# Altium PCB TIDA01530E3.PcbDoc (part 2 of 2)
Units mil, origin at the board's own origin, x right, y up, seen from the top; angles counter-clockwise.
Board outline 3700 x 4450 mil, 2 copper layers (Top Layer, Bottom Layer), stack 62 mil thick; 148 components, 116 nets, 531 pads, 208 vias.
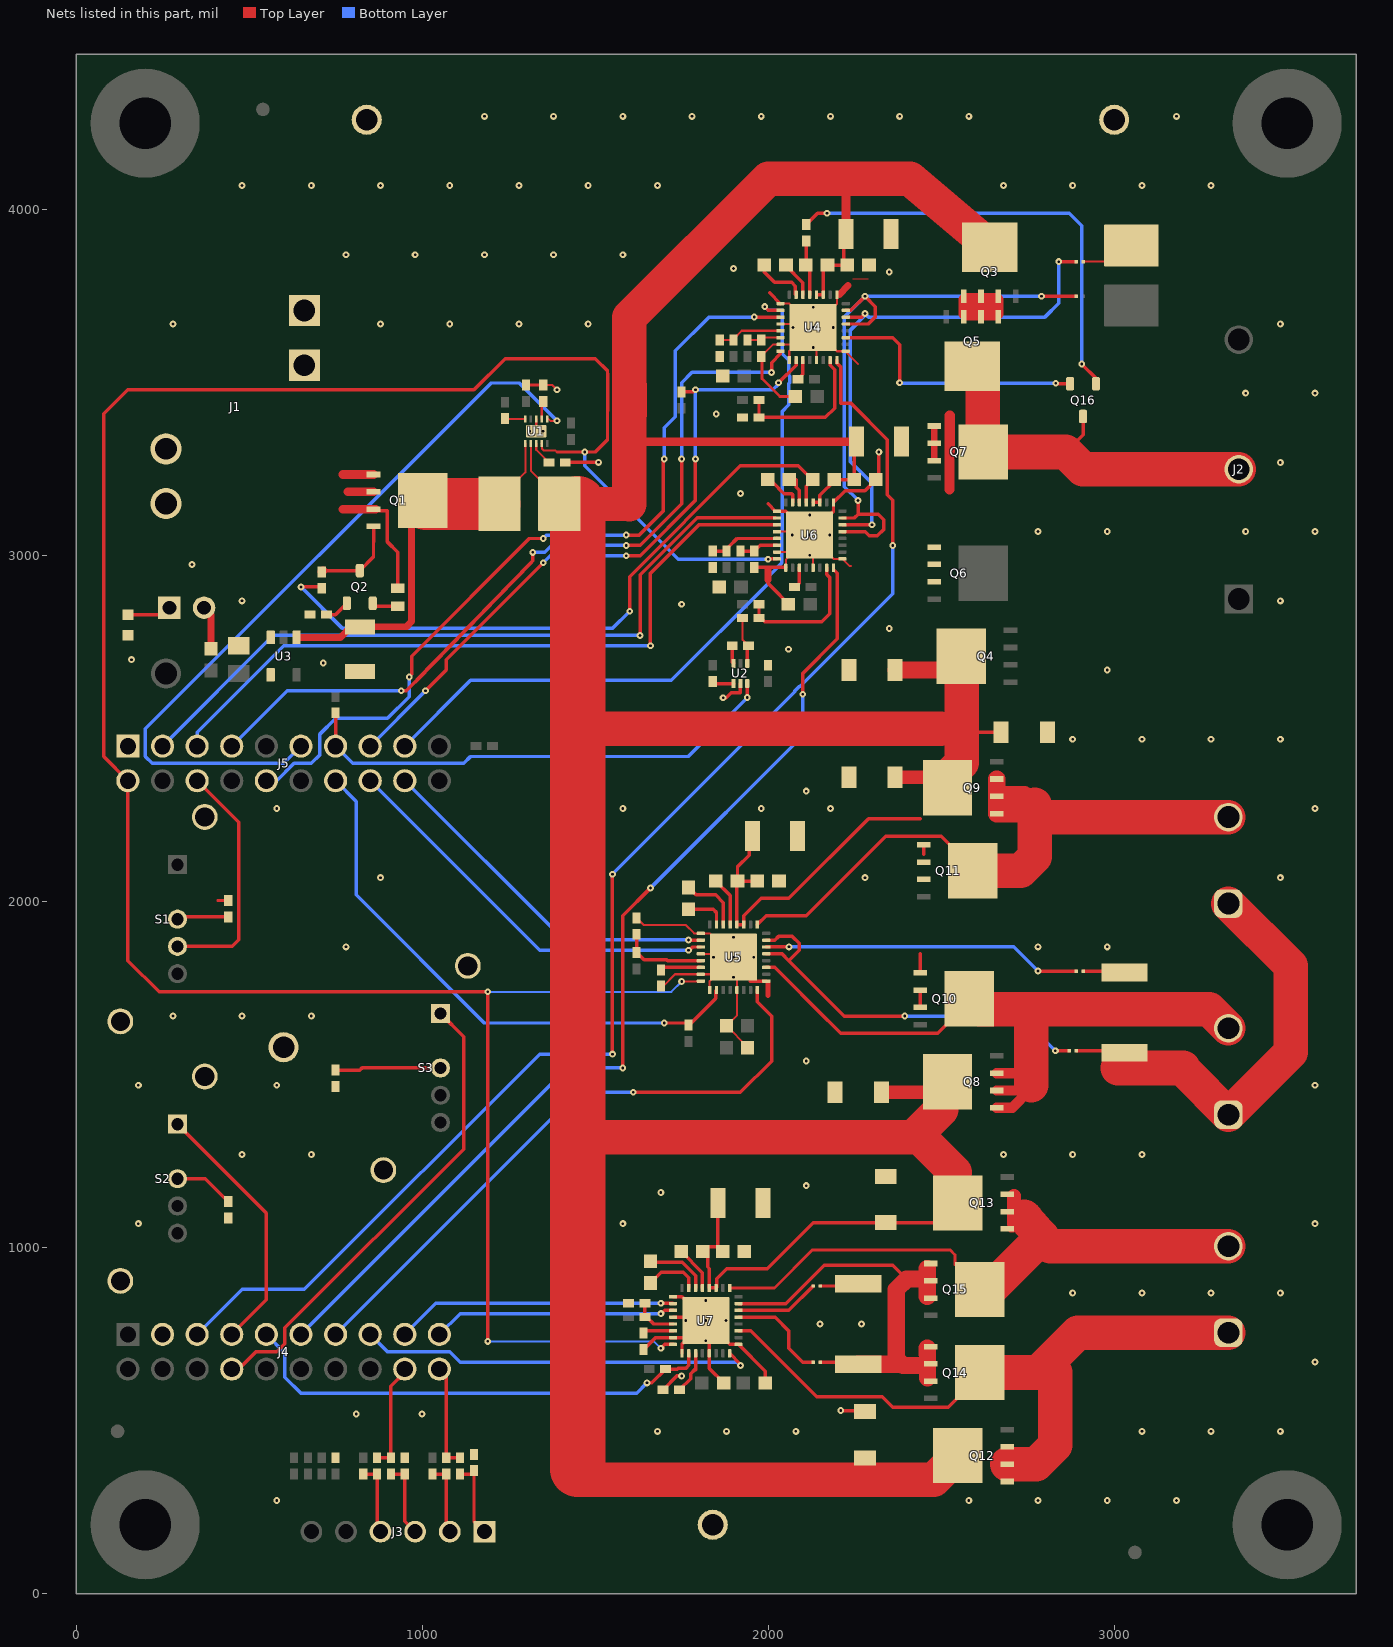
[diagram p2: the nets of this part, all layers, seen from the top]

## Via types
v1: diameter 19.68, hole 7.87, Top Layer to Bottom Layer, 122 vias
v2: diameter 20, hole 8, Top Layer to Bottom Layer, 86 vias

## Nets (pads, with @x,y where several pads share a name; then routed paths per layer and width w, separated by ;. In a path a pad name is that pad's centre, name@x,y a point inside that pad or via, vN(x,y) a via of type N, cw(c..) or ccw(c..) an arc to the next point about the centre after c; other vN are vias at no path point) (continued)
GND: C1.2 C2.2 C3.2 C4.2 C5.2 C6.2 C7.2 C8.2 C10.2 C11.2 C13.2 C14.2 C15.2 C16.2 C18.2 C19.2 C21.2 C22.2 C23.2 C24.2 C26.2 C27.2 C29.2 C30.2 C32.2 C33.2 D2.2 J1.1 J1.1A J4.3 J5.1 NT2.2 NT5.2 NT8.2 Q6.1 Q6.2 Q6.3 Q7.1 Q7.2 Q7.3 Q10.1 Q10.2 Q10.3 Q11.1 Q11.2 Q11.3 R5.2 R6.1 R7.1 R8.2 R14.1 R18.1 R19.1 R26.2 R27.1 R28.1 R32.2 R33.2 R34.1 R35.1 R38.2 R39.2 R41.1 R42.1 R43.1 R46.2 R48.1 R49.2 R51.1 R55.2 S1.G1 S1.G2 S2.G1 S2.G2 S3.G1 S3.G2 TP1.1 TP2.1 TP3.1 TP4.1 U1.8 U1.11 U2.2 U2.4 U3.3 U3.4 U4.1 U4.4 U4.7 U4.9 U4.13 U4.17 U4.25 U4.33 U5.1 U5.4 U5.7 U5.9 U5.13 U5.17 U5.33 U6.1 U6.4 U6.7 U6.9 U6.13 U6.17 U6.25 U6.33 U7.1 U7.4 U7.7 U7.9 U7.13 U7.17 U7.33 | length 5725.9
  Top Layer w0: 2244.41,3800 2290,3800
  Top Layer w6: U1.11@1330,3360 U1.8@1330,3395.43 ; R8.2@1350,3493.62 1376.38,3493.62 v1(1390,3480) ; R33.2@1620,1953.62 1640.62,1933 1762.14,1933 1786.25,1908.9 U5.1@1805.51,1908.9 1831.1,1908.9 U5.33@1890.16,1849.84 ; R32.2@1696.38,1756.38 1730.79,1790.79 U5.7@1805.51,1790.79 1850.79,1790.79 1831.1,1771.1 U5.9@1831.1,1745.51 ; U5.4@1805.51,1849.84 U5.33@1890.16,1849.84 ; R49.2@1926.38,2820 1926.38,2757.24 R6.1@1943.62,2740 ; C15.2@1940,1578.5 1940,1581.5 C16.2@1880,1641.5 1909.84,1671.34 U5.13@1909.84,1745.51 1909.84,1830.16 v1(1900,1840) U5.33@1890.16,1849.84 ; R51.1@1981.93,3574.45 R51.1@1980,3576.38 2014.41,3610.79 U4.7@2035.51,3610.79 U4.33@2080.79,3610.79 ; U5.17@1994.49,1771.1 2000,1765.59 ; U6.1@2021.1,3128.9 U6.1@2025.51,3128.9 ; U6.7@2025.51,3010.79 2070.79,3010.79 v1(2120,3060) 2110.16,3069.84 U6.4@2025.51,3069.84 ; U4.4@2035.51,3669.84 U4.33@2120.16,3669.84 ; U4.1@2035.51,3728.9 2061.1,3728.9 U4.33@2120.16,3669.84 ; U6.9@2050.24,2966.38 U6.9@2051.1,2965.51 2051.1,2988.9 U6.33@2120,3057.8 ; C30.2@2050.7,2860 C30.2@2058.5,2860 ; U4.9@2061.1,3565.51 2061.1,3591.1 U4.33@2080.79,3610.79 ; U6.13@2129.84,2965.51 2129.84,3050.16 2188.9,2991.1 U6.17@2214.49,2991.1 2235.59,2970 2240,2970 ; U4.13@2139.84,3565.51 U4.33@2139.84,3650.16 ; U4.25@2198.9,3754.49 2198.9,3728.9 v1(2130,3660) ; 2260.26,3554 2224.49,3589.77 U4.17@2224.49,3591.1 2198.9,3591.1 U4.33@2139.84,3650.16 ; NT2.2@2910,3850 R18.1@3003.39,3850 ; U4.33@2080.79,3610.79 v1(2130,3660) ; U4.33@2120.16,3669.84 v1(2130,3660) ; v1(2130,3660) U4.33@2139.84,3650.16
  Top Layer w8: 409.69,2003.62 R43.1@440,2003.62 ; R51.1@1981.93,3574.45 1981.93,3511.93 2033.86,3460 C8.2@2078.5,3460
  Top Layer w10: C1.2@1300,3493.62 R8.2@1350,3493.62 ; R5.2@1413.62,3270 v1(1510,3270) ; R39.2@1596.38,840 R39.2@1597.86,840 ; R38.2@1640,706.38 1674.41,740.79 U7.7@1725.51,740.79 U7.33@1769.21,740.79 ; R32.2@1690,1756.38 R32.2@1696.38,1756.38 ; R35.1@1696.38,590 1736.38,630 v1(1750,630) ; U7.4@1725.51,799.84 1810.16,799.84 1751.1,858.9 U7.1@1725.51,858.9 ; U7.9@1751.1,695.51 1751.1,721.1 v1(1820,790) U7.33@1829.84,780.16 ; v1(1870,2590) 1879.13,2590 1893.94,2604.8 1918.96,2604.8 1919.09,2604.94 1919.09,2629.96 U2.2@1920,2630.87 ; C24.2@1871.5,610 1829.84,651.65 U7.13@1829.84,695.51 U7.33@1829.84,780.16 ; U2.4@1939.68,2689.13 R6.1@1939.68,2736.06 ; 1948.74,1771.1 U5.17@1994.49,1771.1 ; R48.1@1960,2966.38 U6.9@2050.24,2966.38 ; C23.2@1991.5,610 1991.5,644.09 U7.17@1914.49,721.1 1888.9,721.1 U7.33@1829.84,780.16 ; 2000,2920 C30.2@2070,2850 ; 2000,3150 U6.1@2021.1,3128.9 ; 2004.41,3760 U4.1@2035.51,3728.9 ; U6.1@2025.51,3128.9 2051.1,3128.9 U6.33@2110.16,3069.84 ; v1(2120,3060) 2188.9,3128.9 U6.25@2188.9,3154.49 2222.83,3188.43 2279.92,3188.43 C33.2@2311.5,3220 ; NT8.2@2150,890 R34.1@2253.86,890 ; v1(2210,530) C21.2@2276.93,530 ; C33.2@2320,3220 v1(2320,3300) ; Q10.3@2439.57,1695 Q10.2@2439.57,1745 ; Q10.1@2439.57,1795 2439.57,1850.43 ; 2449.57,2138.07 Q11.1@2449.57,2165 ; Q7.1@2468.53,3375 Q7.1@2479.57,3375 ; Q7.3@2474.57,3280 Q7.3@2479.57,3275 ; NT5.2@2910,1800 R28.1@2997.89,1800 ; R28.1@3026.14,1800 R28.1@3030,1796.14
  Top Layer w15: 2000,1730 2000,1765.59
  Top Layer w20: 2000,2930 2000,2960 ; 2205.77,3755.49 2231.28,3781 ; Q7.3@2480,3280 Q7.1@2480,3370
  Top Layer w30: 2524.25,3191.93 2525.24,3404.94
  other v1: 810,520 1000,520 1820,731.93 2150,780 2270,780 1761.93,790 1878.07,790 1820,848.07 1690,1160 2110,1180 2110,1540 1900,1781.93 1841.93,1840 1958.07,1840 1900,1898.07 2110,2320 714.24,2690 160,2700 2058.66,2729.74 2350,2790 1750,2860 335,2975 2120,3001.93 2070,3060 2178.07,3060 2120,3118.07 1920,3180 1310.32,3360 1349.69,3360 1850,3410 2130,3601.93 2071.93,3660 2188.07,3660 2130,3718.07 2350,3820 1900,3830
  other v2: 580,270 2580,270 2780,270 2980,270 3180,270 1680,470 1880,470 2080,470 3080,470 3280,470 3480,470 3580,670 2880,870 3080,870 3280,870 3480,870 180,1070 1580,1070 3580,1070 480,1270 680,1270 2680,1270 2880,1270 3080,1270 180,1470 580,1470 3580,1470 280,1670 480,1670 680,1670 780,1870 2780,1870 2980,1870 880,2070 2280,2070 3480,2070 580,2270 1580,2270 1980,2270 2180,2270 3580,2270 2880,2470 3080,2470 3280,2470 3480,2470 2980,2670 480,2870 3480,2870 2780,3070 2980,3070 3380,3070 3580,3070 3480,3270 3380,3470 3580,3470 280,3670 880,3670 1080,3670 1280,3670 1480,3670 3480,3670 780,3870 980,3870 1180,3870 1380,3870 1580,3870 480,4070 680,4070 880,4070 1080,4070 1280,4070 1480,4070 1680,4070 2680,4070 2880,4070 3080,4070 3280,4070 1180,4270 1380,4270 1580,4270 1780,4270 1980,4270 2180,4270 2380,4270 2580,4270 3180,4270
IFAST: J4.11 U6.16 | length 2949.9
  Top Layer w10: v1(1580,1520) 1580,1960 v1(1660,2040) ; v1(2100,2600) 2100,2660 2200,2760 2200,2950 U6.16@2190,2960
  Bottom Layer w10: J4.11@650,750 1420,1520 v1(1580,1520) ; v1(1660,2040) 2100,2480 v1(2100,2600)
IFRONTN: NT2.1 U4.22 U6.22 | length 1548.6
  Top Layer w10: U6.22@2214.96,3090 v1(2300,3090) ; U4.22@2224.96,3690 2270,3690 v1(2280,3700) ; v1(2840,3850) NT2.1@2890,3850
  Bottom Layer w10: v1(2300,3090) 2300,3210 2237.87,3272.13 2237.87,3590 2237.28,3590.59 2237.28,3609.41 2237.87,3610 2237.87,3652.52 2280,3694.65 v1(2280,3700) 2290,3690 2800,3690 2840,3730 v1(2840,3850)
IFRONTP: NT1.1 U4.21 U4.23 U6.21 U6.23 | length 1811.2
  Top Layer w10: U6.21@2214.49,3069.84 2280.71,3069.84 2292.7,3057.85 2315.86,3057.85 2333.95,3075.94 2333.95,3104.06 2318.01,3120 2260,3120 ; U6.23@2214.49,3109.21 2249.21,3109.21 2260,3120 ; U4.21@2224.49,3669.84 2289.84,3669.84 2310,3690 2310,3720 v1(2280,3750) 2239.21,3709.21 U4.23@2224.49,3709.21 ; v1(2260,3160) 2260,3120 ; v1(2790,3750) NT1.1@2890,3750
  Bottom Layer w10: v1(2260,3160) 2220,3200 2220,3582.6 2219.41,3583.19 2219.41,3616.81 2220,3617.4 2220,3690 v1(2280,3750) v1(2790,3750)
IMON_LATCH: J5.11 U1.6 | length 2241.8
  Top Layer w6: U1.6@1360.56,3400 1370.56,3390 v1(1390,3390)
  Bottom Layer w10: J5.11@650,2450 600,2400 220,2400 200,2420 200,2500 1199.39,3499.39 1280.61,3499.39 v1(1390,3390)
IN1F: J5.3 U6.2 | length 2135.7
  Top Layer w10: v1(1630,2770) 1630,2944.72 1795.28,3110 U6.2@2020,3110
  Bottom Layer w10: J5.3@250,2450 570,2770 1620,2770
IN1R: J5.18 U5.2 | length 1045.3
  Top Layer w10: v1@1770.79,1889.21 U5.2@1805.51,1889.21
  Bottom Layer w10: J5.18@950,2350 1410,1890 v1(1770,1890)
IN1S: J5.17 U4.2 | length 2174.1
  Top Layer w10: v1(1990,3720) 2000,3710 2010,3710 ; 2010.79,3709.21 U4.2@2035.51,3709.21
  Bottom Layer w10: J5.17@950,2450 1140,2640 1720,2640 2000,2920 2000,2940 2039.21,2979.21 2039.21,3069.41 2041.1,3071.3 2040.23,3417.08 2060,3436.85 2060,3497.87 2062.72,3500.59 2062.72,3519.41 2060,3522.13 2060,3564.58 2041.1,3583.48 2041.1,3710 2000,3710 v1(1990,3720)
IN1W: J4.17 U7.2 | length 812
  Top Layer w10: v1(1690,840) U7.2@1724.72,840
  Bottom Layer w10: J4.17@950,750 1040,840 v1(1690,840)
IN2F: J5.5 U6.3 | length 2086.5
  Top Layer w10: v1(1660,2740) 1660,2949.44 1800.08,3089.53 U6.3@2025.51,3089.53
  Bottom Layer w10: J5.5@350,2450 350,2490 600,2740 v1(1660,2740)
IN2R: J5.16 U5.3 | length 1162.4
  Top Layer w10: v1(1770,1860) 1772.13,1860 1781.65,1869.53 U5.3@1805.51,1869.53
  Bottom Layer w10: J5.16@850,2350 1340,1860 v1(1770,1860)
IN2S: J5.10 U4.3 | length 2390.8
  Top Layer w10: v1(962.72,2650) 970,2657.28 970,2710 1310,3050 v1(1350,3050) ; v1(1590,3060) 1627.52,3060 1697.52,3130 1697.52,3277.52 v1(1700,3280) ; v1(1960,3690) 1960.47,3689.53 U4.3@2035.51,3689.53
  Bottom Layer w10: J5.10@550,2350 580,2350 630,2400 680,2400 703.66,2423.66 703.66,2483.66 750,2530 900,2530 962.72,2592.72 v1(962.72,2650) ; v1(1350,3050) 1360,3060 v1(1590,3060) ; v1(1700,3280) 1700,3370 1732.13,3402.13 1732.13,3592.13 1830,3690 v1(1960,3690)
IN2W: J4.19 U7.3 | length 704.3
  Top Layer w10: v1(1690,810.16) 1692.28,810.16 1701.65,819.53 U7.3@1725.51,819.53
  Bottom Layer w10: J4.19@1050,750 1110.16,810.16 v1(1690,810.16)
IPUMP: J4.15 U7.16 | length 1155.7
  Top Layer w10: U7.16@1888.9,695.51 1920,664.41 v1(1920,660)
  Bottom Layer w10: J4.15@850,750 900,700 1080,700 1110,670 1910,670 v1(1920,660)
IPUMPH: NT7.1 U7.21 | length 298.6
  Top Layer w10: U7.21@1914.49,799.84 2020.16,799.84 2060,760 2060,710 2100,670 NT7.1@2130,670
IPUMPL: NT8.1 U7.22 | length 244
  Top Layer w10: U7.22@1914.96,820 2060,820 NT8.1@2130,890
IREAR: J4.13 U5.16 | length 1809.8
  Top Layer w10: v1(1610,1450) 1920,1450 2010,1540 2010,1670 1968.9,1711.1 U5.16@1968.9,1745.51
  Bottom Layer w10: J4.13@750,750 1450,1450 v1(1610,1450)
IREARN: NT5.1 U5.22 | length 924
  Top Layer w10: U5.22@1994.96,1870 v1(2060,1870) ; v1(2780,1800) NT5.1@2890,1800
  Bottom Layer w10: v1(2060,1870) 2710,1870 v1(2780,1800)
IREARP: NT3.1 U5.21 U5.23 | length 1162.1
  Top Layer w10: U5.21@1994.49,1849.84 2040.16,1849.84 2060,1830 ; U5.23@1994.49,1889.21 2019.21,1889.21 2030,1900 2070,1900 2090,1880 2090,1860 2060,1830 ; v1(2394.65,1670) 2220,1670 2060,1830 ; v1(2830,1570) NT3.1@2870,1570
  Bottom Layer w10: v1(2394.65,1670) 2730,1670 v1(2830,1570)
ISLOW: J4.5 U4.16 | length 3972.1
  Top Layer w10: v1(1550,1560) v1(1550,2080) ; U4.16@2198.9,3565.51 2198.9,3556.38 2209.8,3545.47 2209.8,3440.2 2239.8,3440.2 2344.06,3335.94 2344.06,3175.94 2360,3160 v1(2360,3030)
  Bottom Layer w10: J4.5@350,750 480,880 660,880 1340,1560 v1(1550,1560) ; 1550,2070 v1(1550,2080) 2077.28,2607.28 2077.28,2609.41 2090.59,2622.72 2092.72,2622.72 2360,2890 v1(2360,3030)
NetC12_1: C12.1 U4.30 | length 105.8
  Top Layer w10: C12.1@2051.5,3840 2051.5,3838.5 2100.47,3789.53 U4.30@2100.47,3754.49
NetC12_2: C12.2 U4.31 | length 132.8
  Top Layer w10: 1988.5,3820 2018.5,3790 2068.07,3790 2078.9,3779.17 2078.9,3756.38 U4.31@2080.79,3754.49
NetC17_2: C17.2 U5.29 | length 142.8
  Top Layer w10: C17.2@1848.5,2060 1890.16,2018.35 U5.29@1890.16,1934.49
NetC20_1: C20.1 U5.30 | length 182
  Top Layer w10: C20.1@1770,2041.5 1791.5,2020 1848.43,2020 1870.47,1997.95 U5.30@1870.47,1934.49
NetC20_2: C20.2 U5.31 | length 119.4
  Top Layer w10: C20.2@1770,1978.5 1841.5,1978.5 1850.79,1969.21 U5.31@1850.79,1934.49
NetC25_2: C25.2 U7.29 | length 131
  Top Layer w10: C25.2@1748.5,990 1810.16,928.35 U7.29@1810.16,884.49
NetC28_1: C28.1 U7.30 | length 178.6
  Top Layer w10: C28.1@1663.07,958.43 1751.57,958.43 1790.47,919.53 U7.30@1790.47,884.49
NetC28_2: C28.2 U7.31 | length 159.9
  Top Layer w10: C28.2@1660,898.5 1691.5,930 1754.72,930 1770.79,913.94 U7.31@1770.79,884.49
NetC34_1: C34.1 U6.30 | length 69.2
  Top Layer w10: 2081.5,3220 2081.5,3198.5 2090.47,3189.53 U6.30@2090.47,3154.49
NetC34_2: C34.2 U6.31 | length 106.1
  Top Layer w10: C34.2@2005.28,3220 2028.94,3196.34 2028.94,3195.97 2036.48,3188.43 2036.85,3188.43 2046.1,3179.17 2068.75,3179.17 2070.79,3177.14 U6.31@2070.79,3154.49
NetD1_2: D1.2 Q2.2 | length 64.3
  Top Layer w10: Q2.2@865.75,2854.41 D1.2@930,2854.41
NetD2_1: D2.1 J8.1 | length 114.6
  Top Layer w10: D2.1@159.53,2830 260,2830 J8.1@270,2840
NetJ8_2: J8.2 R9.2 | length 126.8
  Top Layer w20: J8.2@370,2850 390,2830 R9.2@390,2731.5
NetNT7_2: NT7.2 Q14.1 Q14.2 Q14.3 Q15.1 Q15.2 Q15.3 R34.2 U7.23 | length 1439.2
  Top Layer w10: U7.23@1914.49,838.95 U7.23@1914.49,839.21 2051.01,839.21 2161.79,950 2360,950 2400,910 ; NT7.2@2150,670 R34.2@2253.86,670
  Top Layer w50: R34.2@2260,663.86 2386.14,663.86 ; 2460,940 Q15.2@2460,910 ; 2460.43,625 Q14.2@2460.25,660.1 ; 2386.14,663.86 2370,680 2370,880 2400,910 Q15.2@2460,910 ; 2386.14,663.86 2389.9,660.1 Q14.2@2460.25,660.1 ; Q15.2@2460,910 2460,860 Q15.2@2460,910 ; Q14.2@2460.25,660.1 Q14.2@2460.23,664.95 ; Q14.2@2460.23,664.95 2460,710 Q14.2@2460.23,664.95
NetQ2_1: Q2.1 R7.2 | length 72.5
  Top Layer w10: R7.2@723.62,2830 749.84,2830 Q2.1@782.6,2862.76
NetQ3_1: Q3.1 Q3.2 Q3.3 Q5.1 Q5.2 Q5.3 | length 260
  Top Layer w40: Q5.3@2570,3700 2660,3700 2660,3740 2570,3740 Q5.3@2570,3700
NetQ16_1: Q16.1 R54.1 | length 1285.4
  Top Layer w10: R54.1@2110,3954.86 R54.1@2110,3957.24 2142.76,3990 v1(2170,3990) ; v1(2906,3554) Q16.1@2947.4,3512.6
  Bottom Layer w10: v1(2170,3990) 2870,3990 2906,3954 v1(2906,3554)
NetR4_2: R4.2 U2.1 | length 54.8
  Top Layer w10: R4.2@1845.51,2630.87 U2.1@1900.31,2630.87
NetR5_1: R5.1 U1.3 | length 69.6
  Top Layer w6: U1.3@1330,3324.57 1330,3306.38 R5.1@1366.38,3270
NetR6_2: R6.2 U2.6 | length 52.5
  Top Layer w10: R6.2@1896.38,2740 1896.38,2693.07 U2.6@1900.31,2689.13
NetR8_1: R8.1 U1.7 | length 52.7
  Top Layer w6: U1.7@1345.75,3395.43 1345.75,3442.13 R8.1@1350,3446.38
NetR10_2: R10.2 U1.10 | length 57.6
  Top Layer w6: R10.2@1240.94,3395.43 U1.10@1298.5,3395.43
NetR23_1: R23.1 R26.1 U4.5 | length 188.3
  Top Layer w6: R26.1@1860,3623.62 R23.1@1900,3623.62 1900,3626.56 1923.68,3650.24 1963.68,3650.24 U4.5@2035.51,3650.16 U4.5@2035.51,3650.16
NetR24_2: R24.2 R51.2 U4.6 | length 98.3
  Top Layer w6: R24.2@1940,3623.62 R51.2@1980,3623.62 1986.85,3630.47 U4.6@2035.51,3630.47
NetR29_2: R29.2 R49.1 U6.15 | length 388.4
  Top Layer w10: R49.1@1973.62,2820 R29.2@1973.62,2860 ; R49.1@1980,2820 1990.63,2809.37 2154.65,2809.37 2177.87,2832.6 2177.87,2937.4 2169.21,2946.06 U6.15@2169.21,2965.51
NetR31_2: R31.2 R33.1 U5.5 | length 248
  Top Layer w10: R33.1@1620,1906.38 R31.2@1620,1853.62 1641.38,1832.24 1707.14,1832.24 1709.23,1830.16 U5.5@1805.51,1830.16
NetR32_1: R32.1 U5.6 | length 118.3
  Top Layer w10: R32.1@1690,1803.62 1696.85,1810.47 U5.6@1805.51,1810.47
NetR35_2: R35.2 U7.11 | length 124.1
  Top Layer w10: R35.2@1743.62,590 1775.94,622.32 1775.94,635.94 1788.56,648.56 ; 1790.47,648.56 U7.11@1790.47,695.51
NetR37_1: R37.1 R39.1 U7.5 | length 124.3
  Top Layer w10: R37.1@1643.62,800 1649.39,800 1669.23,780.16 U7.5@1725.51,780.16 ; R37.1@1643.62,805.77 R39.1@1643.62,840
NetR38_1: R38.1 U7.6 | length 81.4
  Top Layer w10: R38.1@1644.09,760.47 U7.6@1725.51,760.47
NetR41_2: R41.2 S2.2 | length 179.3
  Top Layer w10: S2.2@293.31,1200 373.62,1200 R41.2@440,1133.62
  Bottom Layer w10: S2.2@293.31,1200 S2.2@296.93,1203.62
NetR42_2: R42.2 S3.2 | length 305.9
  Top Layer w10: R42.2@750,1513.62 820,1513.62 826.38,1520 S3.2@1053.31,1520
NetR43_2: R43.2 S1.2 | length 149.3
  Top Layer w10: S1.2@293.31,1950 299.69,1956.38 R43.2@440,1956.38
NetR45_1: R45.1 R46.1 U6.5 | length 186.8
  Top Layer w10: R46.1@1840,3013.62 R45.1@1880,3013.62 ; R45.1@1887.84,3027.84 1910,3050 U6.5@2025.51,3050.16
NetR47_2: R47.2 R48.2 U6.6 | length 112.5
  Top Layer w10: R47.2@1920,3013.62 R48.2@1960,3013.62 1976.85,3030.47 U6.6@2025.51,3030.47
NetR50_2: R50.2 R55.1 U4.15 | length 423.5
  Top Layer w10: R50.2@1973.62,3450 R55.1@1973.62,3400 2165.28,3400 2191.93,3426.65 2191.93,3538.07 2179.21,3550.79 U4.15@2179.21,3565.51
NetR52_2: R52.2 U6.11 | length 63.5
  Top Layer w10: R52.2@2076.38,2910 2080,2910 2090.47,2920.47 U6.11@2090.47,2965.51
NetR53_2: R53.2 U4.11 | length 61.3
  Top Layer w10: R53.2@2086.38,3510 2100.47,3524.09 U4.11@2100.47,3565.51
PUMPOK: J4.9 R36.2 U7.10 | length 1400.4
  Top Layer w10: v1(1650,610) 1663.62,610 R36.2@1703.62,650 1737.87,650 1740.59,652.72 1762.72,652.72 1770.79,660.79 U7.10@1770.79,695.51
  Bottom Layer w10: J4.9@550,750 603.66,696.34 603.66,626.34 650,580 1620,580 v1(1650,610)
R_SPRAY: J4.8 S3.1 | length 1379.5
  Top Layer w10: J4.8@450,650 470,650 520,700 580,700 603.66,723.66 603.66,769.19 1120,1285.53 1120,1610.79 S3.1@1053.31,1677.48
R_WIPE: J4.7 S2.1 | length 755.2
  Top Layer w10: S2.1@293.31,1357.48 550,1100.79 550,850 J4.7@450,750
RBG: Q1.4 Q2.3 R40.1 | length 250.6
  Top Layer w10: R40.1@713.62,2957.24 Q2.3@820,2957.24 859.57,2996.81 Q1.4@860,3080
  Top Layer w25: R40.1@710,2953.62 R40.1@713.62,2957.24
REAR_RTN: J6.1 J7.1 NT3.2 R28.2 | length 1269.8
  Top Layer w10: NT3.2@2892,1570 R28.2@3035.86,1570
  Top Layer w100: 3010,1520 3200,1520 ; 3205,1510 J6.1@3330,1385 3510,1565 3510,1815 J7.1@3330,1995
REAROK: J5.14 R30.2 U5.10 | length 1598.8
  Top Layer w10: v1(1700,1650) R30.2@1763.62,1650 ; R30.2@1770,1641.93 1770.85,1642.78 1848.9,1720.83 1848.9,1743.62 U5.10@1850.79,1745.51
  Bottom Layer w10: J5.14@750,2350 810,2290 810,2020 1180,1650 v1(1700,1650)
RPARK1: J4.18 R16.2 R17.2 | length 312.9
  Top Layer w10: R16.2@870,393.62 R17.2@910,393.62 910,600 950,640 J4.18@950,650
RPARK1H: J3.4 R15.2 R16.1 | length 210.5
  Top Layer w10: R15.2@830,346.38 R16.1@870,346.38 870,190 J3.4@880,180
RPARK1L: J3.3 R17.1 R19.2 | length 218.8
  Top Layer w10: R17.1@910,346.38 R19.2@950,346.38 950,210 J3.3@980,180
RPARK2: J4.20 R22.2 R25.2 | length 291.1
  Top Layer w10: J4.20@1050,650 J4.20@1054.69,650 ; J4.20@1070,640 R22.2@1070,393.62 R25.2@1110,393.62
RPARK2H: J3.2 R21.2 R22.1 | length 210.5
  Top Layer w10: R21.2@1030,346.38 R22.1@1070,346.38 1070,190 J3.2@1080,180
RPARK2L: J3.1 R25.1 R27.2 | length 218.8
  Top Layer w10: R25.1@1110,346.38 1150,346.38 1150,210 J3.1@1180,180
SH1R: J6.2 Q8.1 Q8.2 Q8.3 Q10.5 U5.19 | length 1982
  Top Layer w10: U5.19@1994.49,1810.47 2018.97,1810.47 2172.95,1656.49 2173.51,1656.49 2210,1620 2490,1620 Q10.5@2581.69,1711.69
  Top Layer w30: Q8.1@2660.43,1405 2705,1405 2755,1455 Q8.2@2660.43,1455 ; Q8.3@2660.43,1505 2725,1505
  Top Layer w100: Q10.5@2581.69,1720 2611.69,1690 2760,1690 ; 2760,1470 2760,1690 ; J6.2@3330,1635 3275,1690 2760,1690
SH1W: J9.1 Q12.1 Q12.2 Q12.3 Q14.5 U7.19 | length 2157.1
  Top Layer w10: U7.19@1914.49,760.47 1949.53,760.47 2140,570 2330,570 2360,540 2520,540 Q14.5@2611.69,631.69 ; Q14.5@2615.85,635.85 Q14.5@2656.69,595
  Top Layer w100: Q14.5@2611.69,640 2780,640 ; J9.1@3330,755 2895,755 2780,640 ; 2775,375 Q12.2@2690.43,375 2775,375 ; 2775,375 2830,430 2830,640 2780,640
SH2R: J7.2 Q9.1 Q9.2 Q9.3 Q11.5 U5.25 | length 2063.8
  Top Layer w10: U5.25@1968.9,1934.49 1994.41,1960 2110,1960 2340,2190 2500,2190 Q11.5@2591.69,2098.31 ; J7.2@3330,2220 J7.2@3330,2245
  Top Layer w50: Q9.3@2660.43,2355 Q9.2@2660.43,2305 Q9.1@2660.43,2255 2745,2255 2770,2280 ; 2770,2280 2740,2310 2670,2310 2670,2280 2770,2280
  Top Layer w100: Q11.5@2651.69,2090 2730,2090 2770,2130 2770,2280 ; 2805,2245 J7.2@3330,2245
SH2W: J9.2 Q13.1 Q13.2 Q13.3 Q15.5 U7.25 | length 1677.6
  Top Layer w8: U7.25@1888.9,884.49 2018.35,884.49 2127.61,993.75 2526.25,993.75 2540,980 2540,951.69
  Top Layer w10: Q13.1@2690.43,1055 2705,1055 2700,1050 Q13.1@2710,1050
  Top Layer w40: 2710,1070 Q13.3@2710,1150
  Top Layer w100: Q15.5@2611.69,880 2640,880 2791.56,1031.56 2746.71,1082.39 2740,1090 ; 2815,1005 J9.2@3330,1005
SH_SLOW: Q16.2 U4.19 | length 778
  Top Layer w10: U4.19@2224.49,3630.47 2359.53,3630.47 2380,3610 v1(2380,3500) ; v1(2831.36,3498.69) 2832.8,3497.24 Q16.2@2872.6,3497.24 Q16.2@2865.35,3490
  Bottom Layer w10: v1(2380,3500) 2381.31,3498.69 v1(2831.36,3498.69)
SLOW: J5.6 S1.3 | length 694.2
  Top Layer w10: S1.3@293.31,1871.26 451.26,1871.26 470,1890 470,2230 J5.6@350,2350
SLOW_WINDING: J2.2 Q5.5 Q7.5 Q16.3 | length 1090.8
  Top Layer w10: 2860,3300 2910,3350 Q16.3@2910,3402.76
  Top Layer w100: Q7.5@2620,3320 Q5.5@2620,3528.31 ; Q7.5@2621.69,3300 2860,3300 2910,3250 J2.2@3360,3250
SLOWOK: J5.15 R20.2 U4.10 | length 1947.5
  Top Layer w10: v1(1010,2610) 1070,2670 1070,2700 v1(1350,2980) ; v1(1590,3000) 1630,3000 1790,3160 v1(1790,3280) ; R20.2@1750,3473.62 1783.62,3473.62 v1(1790,3480) ; v1(2030,3500) 2080.79,3550.79 U4.10@2080.79,3565.51
  Bottom Layer w10: J5.15@850,2450 v1(1010,2610) ; v1(1350,2980) 1370,3000 v1(1590,3000) ; v1(1790,3280) v1(1790,3480) 2013.86,3480 v1@2030,3496.14
TEMPOK: J5.13 R2.1 U2.3 | length 1435.9
  Top Layer w10: J5.13@750,2440 J5.13@750,2450 R2.1@750,2546.38 ; v1(1939.68,2590.31) U2.3@1939.68,2630.87
  Bottom Layer w10: J5.13@750,2450 800,2400 1120,2400 1140,2420 1770,2420 ; 1770,2420.63 v1(1939.68,2590.31)
VBATT: D1.1 J1.2 J1.2A Q1.1 Q1.2 Q1.3 | length 530.1
  Top Layer w10: Q1.3@864.57,3130 900,3130 900,3040 930,3010 D1.1@930,2905.59
  Top Layer w25: 771.23,3135 Q1.3@859.57,3135 Q1.3@866.14,3135 ; 771.23,3235 Q1.1@859.57,3235 ; 785,3185 Q1.2@859.57,3185
VCPF: C31.2 R40.2 U6.29 | length 1930.6
  Top Layer w10: v1(650,2910) R40.2@706.38,2910 ; v1(1600,2840) 1600,2940 1920,3260 2087.22,3260 2122.22,3225 C31.2@2133.5,3225 ; U6.29@2110.16,3154.49 2110,3154.65 2110,3201.5 C31.2@2128.5,3220
  Bottom Layer w10: v1(650,2910) 770,2790 1550,2790 v1(1600,2840)
VCPS: C9.2 R54.2 U4.29 | length 133.9
  Top Layer w10: C9.2@2110,3850 R54.2@2110,3910 ; U4.29@2120.16,3754.49 C9.2@2120.16,3828.35
VIN+: C4.1 Q1.5 R1.1 U1.1 U3.1 | length 1049.2
  Top Layer w6: R1.1@1223.39,3166.38 1298.5,3241.5 U1.1@1298.5,3324.57
  Top Layer w20: U3.1@637.4,2764.13 764.13,2764.13 794.96,2794.96 C4.1@820,2794.96 954.96,2794.96 970,2810 Q1.5@970,3120
  Top Layer w150: Q1.5@1011.69,3150 R1.1@1210,3150
VMOTOR: C5.1 C6.1 C9.1 C10.1 C11.1 C13.1 C14.1 C17.1 C18.1 C19.1 C21.1 C22.1 C25.1 C26.1 C27.1 C31.1 C32.1 C33.1 Q3.5 Q4.5 Q8.5 Q9.5 Q12.5 Q13.5 R1.2 U1.2 U4.27 U4.28 U5.27 U5.28 U6.27 U6.28 U7.27 U7.28 | length 12658.9
  Top Layer w6: U1.2@1314.25,3324.57 1314.25,3245.75 R1.2@1409.89,3150.11
  Top Layer w10: C26.1@1855.04,1130 1855.04,1003.46 1824.96,1003.46 1824.96,945.04 1829.84,940.16 U7.28@1829.84,884.49 U7.27@1849.53,884.49 1851.42,886.38 1851.42,911.42 1880,940 1996.93,940 2130,1073.07 Q13.5@2491.38,1073.07 ; C17.1@1909.84,2058.35 U5.28@1909.84,1934.49 U5.27@1929.53,1934.49 1929.53,1959.53 1980,2010 2060,2010 2290,2240 2440,2240 ; C18.1@1945.04,2220 1945.04,2135.04 1911.5,2101.5 C17.1@1911.5,2060 C19.1@1968.5,2060 ; U6.28@2129.84,3154.49 U6.27@2149.53,3154.49 2149.53,3174.43 2195.1,3220 C33.1@2248.5,3220 2248.5,3323.46 C32.1@2255.04,3330 ; U4.28@2139.84,3754.49 U4.27@2159.53,3754.49 2159.53,3828.03 C9.1@2171.5,3840 2218.5,3840 2218.5,3886.54 ; 2560,2490 C5.1@2673.07,2490
  Top Layer w25: 1598.64,3330 C32.1@2255.04,3330 ; C10.1@2225.04,3930 2225.04,4085.04
  Top Layer w40: C14.1@2326.93,1450 Q8.5@2488.31,1450 ; C13.1@2366.93,2360 Q9.5@2488.31,2360
  Top Layer w50: C6.1@2370,2670 Q4.5@2560,2670
  Top Layer w100: R1.2@1409.89,3150.11 1450,3149.94 1598.64,3149.32 1598.64,3330 1598.64,3393.65 1598.75,3393.76 1598.75,3408.08 1599.46,3408.8 1599.46,3491.2 1598.75,3491.92 1598.75,3552.62 1598.64,3552.73 1598.64,3688.64 2000,4090 2410,4090 Q3.5@2610,3920 ; 1450,330 2478.31,330 Q12.5@2548.31,400 ; 1450,1320 2437.64,1320 ; 1450,2500 2498.31,2500 ; 2500,1400 2428.82,1328.82 2437.64,1320 ; Q9.5@2518.31,2360 2560,2401.69 2560,2490 Q4.5@2560,2670 ; 2538.82,1218.82 2437.64,1320 ; Q13.5@2548.31,1120 Q13.5@2548.31,1130
  Top Layer w160: 1450,360 1450,3149.94 R1.2@1450,3150
WAKE: J5.2 U1.4 U5.8 U6.8 U7.8 | length 7538.7
  Top Layer w6: U1.4@1345.75,3324.57 1346.68,3323.63 1346.68,3309.31 1352.15,3303.85 1386.15,3303.85 1390,3300 ; v1(1750,1770) U5.8@1804.41,1770 ; v1(2000,2990) v1@2001.1,2991.1
  Top Layer w10: v1(1190,730) v1(1190,1740) 240,1740 150,1830 J5.2@150,2350 80,2420 80,3410 150,3480 1150,3480 1240,3570 1500,3570 1535.76,3534.24 1535.76,3526.69 1535.87,3526.58 1535.87,3465.87 1536.59,3465.16 1536.59,3434.84 1535.87,3434.13 1535.87,3419.8 1535.76,3419.69 1535.76,3335.76 1500,3300 v1(1470,3300) 1390,3300 ; v1(1690,710) 1701.1,721.1 U7.8@1725.51,721.1 ; v1@2001.1,2991.1 U6.8@2025.51,2991.1
  Bottom Layer w6: v1(1190,730) 1670,730 v1(1690,710) ; v1(1190,1740) 1720,1740 v1(1750,1770)
  Bottom Layer w10: v1(1470,3300) 1470,3260 1740,2990 v1(2000,2990)
WAKE_SLOW: J5.7 U4.8 | length 2301.7
  Top Layer w10: v1(940,2610) 954.26,2610 971.54,2627.28 972.13,2627.28 985.43,2640.59 985.43,2641.18 1314.86,2980 1320,2985.14 v1(1320,3010) ; v1(1590,3030) 1630,3030 1750,3150 v1(1750,3280) ; v1(2010,3530) 2010,3558.06 2035.51,3583.57 U4.8@2035.51,3591.1
  Bottom Layer w10: J5.7@450,2450 610,2610 v1(940,2610) ; v1(1320,3010) 1354.72,3010 1374.72,3030 v1(1590,3030) ; v1(1750,3280) 1750,3500 1780,3530 v1(2010,3530)
pads on no net: FID1.1 FID2.1 FID3.1 H1.1 H2.1 H3.1 H4.1 J4.1 J4.4 J4.10 J4.12 J4.16 J5.9 J5.12 J5.20 S1.4 S2.3 S2.4 S3.3 U3.2 U4. U4.24 U4.26 U4.32 U5. U5.32 U6. U6.24 U6.26 U6.32 U7. U7.32

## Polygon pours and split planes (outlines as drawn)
GND on Top Layer "TOP_LAYER_GND_P004" (solid, remove dead copper, pour order 4): 50,50 50,4400 3650,4400 3650,50
VBATT on Top Layer "TOP_LAYER_VBATT_P000" (solid, remove dead copper, pour order 0): 180,3400 180,3060 810,3060 810,3400
GND on Bottom Layer "BOTTOM_LAYER_GND_P002" (solid, remove dead copper, pour order 2): 50,50 50,4400 3650,4400 3650,50

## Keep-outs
Keep-Out Layer:
  text ".Layer_Name" at 577,-858.49 h60

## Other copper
Top Layer:
  text ".Layer_Name" at 577,-858.49 h60
Bottom Layer:
  text ".Layer_Name" at 577,-858.49 h60

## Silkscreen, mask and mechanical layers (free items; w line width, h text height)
Top Overlay:
  text "TIDA-01530 E3" at 1820,4110 h120
  text "FRONT" at 3270,3850 h100
  text "GND" at 790,3710 h100
  text "RETURN" at 2810,3580 h100
  text "VBATT" at 780,3410 h100
  text "SLOW" at 2890,3220 h100
  text "FAST" at 2900,2840 h100
  text "REAR2" at 3240,2380 h100
  text "FAST" at 520,2110 h100
  text "FRONT" at 30,2080 h100 r270
  text "SLOW" at 520,1920 h100
  text "OFF" at 470,1710 h100
  text "REAR" at 1230,1700 h100
  text "SPRAY" at 790,1630 h100 r270
  text "OFF" at 1190,1540 h72.83
  text "FRONT" at 1190,1380 h100
  text "ON" at 460,1320 h100
  text "REAR" at 30,1310 h100 r270
  text "REAR1" at 3240,1160 h100
  text "OFF" at 440,940 h100
  text "SPRAY PUMP" at 3090,520 h100
  text "PARK  / INPUTS" at 1270,70 h100
  text "H F L" at 620,10 h60
  text "H R L" at 830,10 h60
  text "H R L" at 1050,10 h60
  text ".Layer_Name" at 577,-858.49 h60
Bottom Overlay:
  region: 2050,4060 1750,4060 1750,3960 2050,3960
  text ".Layer_Name" at 577,-858.49 h60
Top Paste:
  text ".Layer_Name" at 577,-858.49 h60
Bottom Paste:
  text ".Layer_Name" at 577,-858.49 h60
Top Solder:
  text ".Layer_Name" at 577,-858.49 h60
  text ".Layer_Name" at 577,-858.49 h60
Bottom Solder:
  text ".Layer_Name" at 577,-858.49 h60
Drill Guide:
  text ".Layer_Name" at 577,-858.49 h60
M1 Board Outline:
  the board outline again, w10
  text ".Layer_Name" at 577,-858.49 h60
M2 Board Dimensions:
  rectangle: 0,-275 125,-150
  rectangle: 125,-400 500,-275
  lines w7: 0,-275 1000,-275 ; 125,-400 125,-150 ; 250,-400 250,-150 ; 500,-400 500,-150 ; 750,-400 750,-150 ; 0,-400 1000,-400 1000,-150 0,-150 0,-400
  text ".Layer_Name" at 577,-858.49 h60
M3 3D STEP Top:
  text ".Layer_Name" at 577,-858.49 h60
M4 3D STEP Bottom:
  text ".Layer_Name" at 577,-858.49 h60
M5 Assembly Top:
  lines w10: -292,-930.17 6308,-930.17 ; -292,-726.83 6310,-726.83 ; -292,-523.5 -292,-1133.5 3713,-1133.5 6310,-1133.5 6310,-523.5 -291.5,-523.5 -291.5,-1133.5 1284,-1133.5 ; 2173,-1133.5 2173,-523.5 ; 3440,-726.83 3440,-523.5 ; 4280,-726.83 4280,-523.5 ; 4902,-1140 4902,-937.17
  text "J4 and J5 are mounted on the BOTTOM of the board." at 4510,1680 h200
  text "COMPONENTS MARKED 'DNP' SHOULD NOT BE POPULATED." at 1153.5,-318.5 h60
  text "ASSEMBLY VARIANT:" at 1153,-434 h60
  text ".VariantName" at 2189,-434 h60
  text "PCB VIEWED FROM TOP SIDE" at -228.5,-655.67 h60
  text "BOARD #:" at 2248,-655.67 h60
  text ".PRJ_Number" at 2793.5,-655.67 h60
  text "REV:" at 3638,-655.67 h60
  text ".PCB_Rev" at 3929.5,-655.67 h60
  text "SVN REV:" at 4476,-655.67 h60
  text ".VersionControl_RevNumber" at 4982,-655.67 h60
  text "TID #:" at 2248,-859 h60
  text ".TID" at 2793.5,-859 h60
  text "PLOT NAME =" at -228.5,-1064.34 h60
  text ".plot_File_Name" at 577,-1064.34 h60
  text "GENERATED    :" at 2250,-1064.34 h60
  text ".Print_Date" at 3119.5,-1064.34 h60
  text ".Print_Time" at 3848.5,-1064.34 h60
  text "TEXAS INSTRUMENTS" at 5113,-1064.34 h60
M6 Assembly Bottom:
  lines w10: -292.5,-727.33 6309.5,-727.33 ; -290.5,-930.67 6309.5,-930.67 ; 1115.5,-1140.5 1115.5,-937.67 ; 1737.5,-727.33 1737.5,-524 ; 2577.5,-727.33 2577.5,-524 ; 3844.5,-1134 3844.5,-524 ; 4733.5,-1134 6309,-1134 6309,-524 -292.5,-524 -292.5,-1134 2304.5,-1134 6309.5,-1134 6309.5,-524
  text "COMPONENTS MARKED 'DNP' SHOULD NOT BE POPULATED." at 6102,-318 h60
  text ".VariantName" at 5058,-434 h60
  text "ASSEMBLY VARIANT:" at 6097,-434 h60
  text ".VersionControl_RevNumber" at 1035.5,-656.17 h60
  text "SVN REV:" at 1541.5,-656.17 h60
  text ".PCB_Rev" at 2088,-656.17 h60
  text "REV:" at 2379.5,-656.17 h60
  text ".PRJ_Number" at 3224,-656.17 h60
  text "BOARD #:" at 3769.5,-656.17 h60
  text "PCB VIEWED FROM BOTTOM SIDE" at 6246,-656.17 h60
  text ".TID" at 3224,-859.5 h60
  text "TID #:" at 3769.5,-859.5 h60
  text "TEXAS INSTRUMENTS" at 904.5,-1064.84 h60
  text ".Print_Time" at 2169,-1064.84 h60
  text ".Print_Date" at 2898,-1064.84 h60
  text "GENERATED    :" at 3767.5,-1064.84 h60
  text ".plot_File_Name" at 5440.5,-1064.84 h60
  text "PLOT NAME =" at 6246,-1064.84 h60
M9 Title Sheet:
  drawing of 57 lines, arcs and shapes, not listed
  text "1" at 739.84,8036.5 h70
  text "2" at 3235.5,8036.5 h70
  text "3" at 5724.84,8036.5 h70
  text "4" at 8231.51,8036.5 h70
  text "5" at 10730.5,8036.5 h70
  text "6" at 13235.5,8036.5 h70
  text "A" at -416.5,6893.5 h70
  text "A" at 14383.5,6893.5 h70
  text "B" at -416.5,4513.5 h70
  text "B" at 14383.5,4513.5 h70
  text "C" at -416.5,2138.5 h70
  text "C" at 14383.5,2138.5 h70
  text "PROJECT TITLE:" at 11343.5,277.5 h45
  text ".PRJ_Title" at 11393.5,144.17 h70
  text "DESIGNED FOR:" at 11343.5,-23.5 h45
  text ".PRJ_Customer" at 11393.5,-163.5 h70
  text "D" at -416.5,-231.5 h70
  text "D" at 14383.5,-231.5 h70
  text "FILE NAME:" at 11343.5,-323.5 h45
  text ".PCB_File_Name_No_Path" at 11393.5,-443.5 h70
  text "Texas Instruments (TI) and/or its licensors do not warrant the accuracy or completeness of this specification" at 6374,-605.34 h45
  text "ENGINEER:" at 11343.5,-613.5 h45
  text "LAYOUT BY:" at 12848.5,-613.5 h45
  text "or any information contained therein. TI and/or its licensors do not warrant that this design will meet" at 6329.01,-718 h45
  text ".PRJ_Engineer" at 11393.5,-768.49 h70
  text ".PCB_Layout" at 12899,-768.49 h70
  text "the specifications, will be suitable for your application or fit for any particular purpose, or will operate in" at 6329.01,-830.67 h45
  text ".Layer_Name" at 577,-858.49 h60
  text "ALTIUM DESIGNER VERSION:" at 12848.5,-923.5 h45
  text "an implementation. TI and/or its licensors do not warrant that the design is production worthy. You should" at 6329.01,-943.33 h45
  text "completely validate and test your design implementation to confirm the system functionality for your application." at 6374,-1056 h45
  text ".print_Scale" at 11393.5,-1056.83 h70
  text ".Application_BuildNumber" at 12899,-1056.83 h70
  text "1" at 739.84,-1263.5 h70
  text "2" at 3235.5,-1263.5 h70
  text "3" at 5724.84,-1263.5 h70
  text "4" at 8231.51,-1263.5 h70
  text "5" at 10730.5,-1263.5 h70
  text "6" at 13235.5,-1263.5 h70
M10 Fab Notes:
  drawing of 173 lines, arcs and shapes, not listed
  text "DESIGN INFORMATION" at 12378.02,6201 h60
  text "MIN. TRACK WIDTH:" at 11733.46,6021 h60
  text "8" at 12829.7,6021 h60
  text "MIL" at 12984.46,6021 h60
  text "MIN. CLEARANCE:" at 11733.46,5889 h60
  text "0.2" at 12769.7,5889 h60
  text "mm" at 12984.46,5889 h60
  text "MIN. VIA PAD SIZE:" at 11733.46,5757 h60
  text "24" at 12799.71,5757 h60
  text "MIL" at 12984.46,5757 h60
  text "0.05mm (2MIL)" at 12428.46,5615.29 h60
  text "MINIMUM ANNULAR RING" at 11404.23,5611 h60
  text "EXTERNAL" at 13136.46,5611 h60
  text "PER" at 11604.23,5493 h60
  text "IPC-D-275 CLASS 2 LEVEL C" at 11824.23,5493 h60
  text "MIL, HOLES" at 13312.46,5380.71 h60
  text "+/-" at 12920,5380 h60
  text "+/-" at 13774,5380 h60
  text "REGISTRATION TOLERANCES:" at 11404.23,5375 h60
  text "METAL" at 12604,5375 h60
  text "5" at 13180.2,5375 h60
  text "3" at 14013.2,5375 h60
  text "MIL" at 14129.46,5375 h60
  text "+/-" at 13774,5262 h60
  text "HOLE SIZE TOLERANCE (UNLESS OTHERWISE SPECIFIED):" at 11404.23,5257 h60
  text "3" at 14013.2,5257 h60
  text "MIL" at 14129.46,5257 h60
  text "MATERIAL:" at 11329.46,5047.54 h60
  text "FR-4 High Tg" at 12315.9,4907.21 h60
  text "FR-408" at 11750.46,4898.64 h60
  text "OTHER" at 13238.46,4898.64 h60
  text "X" at 12161,4895 h60
  text "62 MIL (1.6mm) +/-10%" at 12070.56,4735.92 h60
  text "THICKNESS:" at 11404.23,4731.64 h60
  text "X" at 11942.4,4731.64 h60
  text "OTHER" at 13355.46,4731.64 h60
  text "TOLERANCE:" at 11404.23,4573.64 h60
  text "X" at 12243.53,4573.64 h60
  text "ANSI IPC-6012 TYPE 3 CLASS 2" at 12430.48,4573.64 h60
  text "OTHER +/-" at 12430.46,4417.64 h60
  text "BOW & TWIST:" at 11404.23,4260.64 h60
  text "X" at 12243.53,4260.64 h60
  text "ANSI IPC-6012 TYPE 3 CLASS 2" at 12430.48,4260.64 h60
  text "OTHER +/-" at 12430.46,4102.13 h60
  text "DRILLING:" at 11329.46,3963.64 h60
  text "REFERENCE:" at 11404.23,3846.64 h60
  text "X" at 12052.46,3846.64 h60
  text "AS SHOWN" at 12239.46,3846.64 h60
  text "X" at 12953.46,3846.64 h60
  text "NC_DRILL FILES" at 13090.46,3846.64 h60
  text "PTH COPPER THICKNESS:" at 11404.23,3688.64 h60
  text "X" at 12534.46,3688.64 h60
  text "20-30 um" at 12671.46,3688.64 h60
  text "OTHER" at 13388.46,3688.64 h60
  text "BOARD FINISH:" at 11329.46,3529.64 h60
  text "SILKSCREEN:" at 11484.68,3411.64 h60
  text "X" at 12433.46,3411.64 h60
  text "TOP" at 12559.46,3411.64 h60
  text "X" at 12943.46,3411.64 h60
  text "BOTTOM" at 13070.46,3411.64 h60
  text "SILKSCREEN COLOR:" at 11484.68,3244.64 h60
  text "X" at 12432.42,3244.64 h60
  text "WHITE" at 12559.46,3244.64 h60
  text "OTHER" at 13070.46,3244.64 h60
  text "X" at 12563.42,3085.44 h60
  text "GREEN" at 12690.46,3085.44 h60
  text "OTHER" at 13308.46,3085.44 h60
  text "SOLDER RESIST COLOR:" at 11484.68,3074.64 h60
  text "X" at 12563.42,2915.44 h60
  text "MATTE" at 12690.46,2915.44 h60
  text "SEMI-GLOSS" at 13308,2914.8 h60
  text "IMMERSION GOLD (ENIG)" at 12390.46,2726.92 h60
  text "ENEPIG" at 13728,2723.64 h60
  text "SURFACE FINISH:" at 11329.46,2722.64 h60
  text "X" at 12203.51,2722.64 h60
  text "IMM. TIN/SILVER OR EQUIV" at 11659,2565.64 h60
  text "OTHER" at 13090.46,2565.64 h60
  text "ARRAY/PANEL:" at 11329.46,2386.64 h60
  text "CUT AND TRIM PER M1 BOARD OUTLINE" at 12390.46,2382.35 h60
  text "N.C. ROUTE" at 12390.46,2230.64 h60
  text "X" at 13069.46,2230.64 h60
  text "V. SCORE" at 13256.46,2230.64 h60
  text "CERTIFICATION:" at 11329.46,2093.64 h60
  text "MATERIALS AND WORKMANSHIP FOR ALL PCBS" at 12054.46,2093.64 h60
  text "TO MEET OR EXCEED THE REQUIREMENTS OF:" at 12054.46,1995.64 h60
  text "X" at 11680.96,1859.13 h60
  text "ANSI IPC-A-600F CLASS ->" at 11819.96,1859.13 h60
  text "X" at 13459.02,1859.13 h60
  text "2" at 13577.96,1859.14 h60
  text "1" at 13262.96,1857.64 h60
  text "3" at 13931.96,1857.64 h60
  text "X" at 12495.02,1699.64 h60
  text "RoHS" at 12631.96,1699.64 h60
  text "OTHER" at 13276.36,1699.64 h60
  text "PER ORDER" at 13673.42,1699.64 h60
  text "ALL BOARDS MUST MEET OR EXCEED UL94-V0 REQUIREMENTS." at 11357,1534 h60
  text "PCB MUST BEAR THE UL94V-0 UL REGISTERED MATERIAL ID NUMBER" at 11357,1414 h60
  text "ADDITIONAL REQUIREMENTS:" at 11329.46,1240.64 h60
  text "MICROSECTION:" at 11404.23,1125.64 h60
  text "YES" at 12309.96,1125.64 h60
  text "REQUIRED" at 13171.46,969.49 h60
  text "BARE BOARD ELEC. TEST:" at 11404.23,966.64 h60
  text "NONE" at 12709.96,966.64 h60
  text "X" at 13044.46,966.64 h60
  text "PER ORDER" at 13763.46,966.64 h60
  text ".Layer_Name" at 577,-858.49 h60
M11 Gerber Information:
  lines w10: -292,-930.17 6308,-930.17 ; -292,-726.83 6310,-726.83 ; -292,-523.5 -292,-1133.5 3713,-1133.5 6310,-1133.5 6310,-523.5 -291.5,-523.5 -291.5,-1133.5 1284,-1133.5 ; 2173,-1133.5 2173,-523.5 ; 3440,-726.83 3440,-523.5 ; 4280,-726.83 4280,-523.5 ; 4902,-1140 4902,-937.17
  text "ALL ARTWORK VIEWED FROM TOP SIDE" at -228.5,-655.67 h60
  text "BOARD #:" at 2248,-655.67 h60
  text ".PRJ_Number" at 2793.5,-655.67 h60
  text "REV:" at 3638,-655.67 h60
  text ".PCB_Rev" at 3929.5,-655.67 h60
  text "SVN REV:" at 4476,-655.67 h60
  text ".VersionControl_RevNumber" at 4982,-655.67 h60
  text "LAYER NAME =" at -228.5,-858.49 h60
  text "TID #:" at 2248,-859 h60
  text ".TID" at 2793.5,-859 h60
  text "PLOT NAME =" at -228.5,-1064.34 h60
  text ".plot_File_Name" at 577,-1064.34 h60
  text "GENERATED    :" at 2250,-1064.34 h60
  text ".Print_Date" at 3119.5,-1064.34 h60
  text ".Print_Time" at 3848.5,-1064.34 h60
  text "TEXAS INSTRUMENTS" at 5113,-1064.34 h60
M12 Stackup:
  drawing of 191 lines, arcs and shapes, not listed
  text "Layer" at 9790.34,7830 h60
  text "Name" at 10200.26,7830 h60
  text "Material" at 11130,7830 h60
  text "Thickness" at 11989.77,7830 h60
  text "Constant" at 12639.6,7830 h60
  text "Board Layer Stack" at 13209.46,7830 h60
  text "1" at 9790.34,7710 h60
  text "Top Overlay" at 10200.26,7710 h60
  text "2" at 9790.34,7590 h60
  text "Top Solder" at 10200.26,7590 h60
  text "Solder Resist" at 11130,7590 h60
  text "0.40mil" at 11989.77,7590 h60
  text "3.5" at 12639.6,7590 h60
  text "3" at 9790.34,7470 h60
  text "Top Layer" at 10200.26,7470 h60
  text "Copper" at 11130,7470 h60
  text "1.40mil" at 11989.77,7470 h60
  text "4" at 9790.34,7350 h60
  text "Dielectric1" at 10200.26,7350 h60
  text "FR-4" at 11130,7350 h60
  text "59.20mil" at 11989.77,7350 h60
  text "4.8" at 12639.6,7350 h60
  text "5" at 9790.34,7230 h60
  text "Bottom Layer" at 10200.26,7230 h60
  text "Copper" at 11130,7230 h60
  text "1.40mil" at 11989.77,7230 h60
  text "6" at 9790.34,7110 h60
  text "Bottom Solder" at 10200.26,7110 h60
  text "Solder Resist" at 11130,7110 h60
  text "0.40mil" at 11989.77,7110 h60
  text "3.5" at 12639.6,7110 h60
  text "7" at 9790.34,6990 h60
  text "Bottom Overlay" at 10200.26,6990 h60
  text ".Layer_Name" at 577,-858.49 h60
M13 Component Bodies Top:
  text ".Layer_Name" at 577,-858.49 h60
M14 Component Bodies Bottom:
  text ".Layer_Name" at 577,-858.49 h60
M15 Courtyards Top:
  text ".Layer_Name" at 577,-858.49 h60
M16 Courtyards Bottom:
  text ".Layer_Name" at 577,-858.49 h60
Drill Drawing:
  circle w10: c5348.65,3204.18 r22.05
  circle w10: c5348.65,2906.54 r13.23
  circle w10: c5348.65,2906.54 r22.05
  lines w10: 5326.6,2300.25 5337.63,2300.25 5337.63,2289.23 5359.68,2289.23 5359.68,2300.25 5370.7,2300.25 5370.7,2322.3 5359.68,2322.3 5359.68,2333.32 5337.63,2333.32 5337.63,2322.3 5326.6,2322.3 5326.6,2300.25 ; 5326.6,2432.53 5370.7,2432.53 5348.65,2388.44 5326.6,2432.53 ; 5326.6,2531.75 5370.7,2531.75 5348.65,2487.65 5326.6,2531.75 ; 5326.6,2597.89 5337.63,2597.89 5348.65,2586.86 5359.68,2597.89 5370.7,2597.89 5359.68,2608.91 5370.7,2619.93 5359.68,2619.93 5348.65,2630.96 5337.63,2619.93 5326.6,2619.93 5337.63,2608.91 5326.6,2597.89 ; 5326.6,2686.07 5326.6,2697.1 5337.63,2708.12 5326.6,2719.14 5326.6,2730.17 5337.63,2730.17 5348.65,2719.14 5359.68,2730.17 5370.7,2730.17 5370.7,2719.14 5359.68,2708.12 5370.7,2697.1 5370.7,2686.07 5359.68,2686.07 5348.65,2697.1 5337.63,2686.07 5326.6,2686.07 ; 5326.6,2785.29 5348.65,2796.31 5370.7,2785.29 5359.68,2807.33 5370.7,2829.38 5348.65,2818.36 5326.6,2829.38 5337.63,2807.33 5326.6,2785.29 ; 5326.6,3005.75 5348.65,2983.71 5370.7,3005.75 5348.65,3027.8 5326.6,3005.75 ; 5326.6,3082.92 5370.7,3082.92 5370.7,3127.01 5326.6,3127.01 5326.6,3082.92 ; 5326.6,3281.34 5370.7,3281.34 5370.7,3325.43 5326.6,3325.43 5326.6,3281.34 ; 5335.42,2423.72 5361.88,2423.72 5348.65,2397.26 5335.42,2423.72 ; 5335.42,3091.74 5361.88,3091.74 5361.88,3118.19 5335.42,3118.19 5335.42,3091.74
  lines w12: 5286,2259.47 8395.46,2259.47 ; 5286,3350.79 8395.46,3350.79 ; 5601.13,2160.26 5601.13,3450 ; 5917.88,2160.26 5917.88,3450 ; 6538.9,2160.26 6538.9,3450 ; 6782.83,2160.26 6782.83,3450 ; 7142.73,2160.26 7142.73,3450 ; 7851.88,2160.26 7851.88,3450 ; 5286,2160.26 8395.46,2160.26 8395.46,3450 5286,3450 5286,2160.26
  text "Symbol" at 5345.53,3380.55 h72
  text "Quantity" at 5630.9,3380.55 h72
  text "Finished Hole Size" at 5947.64,3380.55 h72
  text "Plated" at 6568.66,3380.55 h72
  text "Hole Type" at 6812.59,3380.55 h72
  text "Drill Layer Pair" at 7172.49,3380.55 h72
  text "Hole Tolerance" at 7881.64,3380.55 h72
  text "122" at 5630.9,3281.34 h60
  text "7.87mil (0.200mm)" at 5947.64,3281.34 h60
  text "PTH" at 6568.66,3281.34 h60
  text "Round" at 6812.59,3281.34 h60
  text "Top Layer - Bottom Layer" at 7172.49,3281.34 h60
  text "86" at 5630.9,3182.13 h60
  text "8.00mil (0.203mm)" at 5947.64,3182.13 h60
  text "PTH" at 6568.66,3182.13 h60
  text "Round" at 6812.59,3182.13 h60
  text "Top Layer - Bottom Layer" at 7172.49,3182.13 h60
  text "12" at 5630.9,3082.92 h60
  text "35.43mil (0.900mm)" at 5947.64,3082.92 h60
  text "PTH" at 6568.66,3082.92 h60
  text "Round" at 6812.59,3082.92 h60
  text "Top Layer - Bottom Layer" at 7172.49,3082.92 h60
  text "2" at 5630.9,2983.71 h60
  text "40.00mil (1.016mm)" at 5947.64,2983.71 h60
  text "PTH" at 6568.66,2983.71 h60
  text "Round" at 6812.59,2983.71 h60
  text "Top Layer - Bottom Layer" at 7172.49,2983.71 h60
  text "6" at 5630.9,2884.5 h60
  text "43.31mil (1.100mm)" at 5947.64,2884.5 h60
  text "PTH" at 6568.66,2884.5 h60
  text "Round" at 6812.59,2884.5 h60
  text "Top Layer - Bottom Layer" at 7172.49,2884.5 h60
  text "40" at 5630.9,2785.29 h60
  text "47.24mil (1.200mm)" at 5947.64,2785.29 h60
  text "PTH" at 6568.66,2785.29 h60
  text "Round" at 6812.59,2785.29 h60
  text "Top Layer - Bottom Layer" at 7172.49,2785.29 h60
  text "6" at 5630.9,2686.07 h60
  text "55.12mil (1.400mm)" at 5947.64,2686.07 h60
  text "PTH" at 6568.66,2686.07 h60
  text "Round" at 6812.59,2686.07 h60
  text "Top Layer - Bottom Layer" at 7172.49,2686.07 h60
  text "4" at 5630.9,2586.86 h60
  text "62.50mil (1.587mm)" at 5947.64,2586.86 h60
  text "PTH" at 6568.66,2586.86 h60
  text "Round" at 6812.59,2586.86 h60
  text "Top Layer - Bottom Layer" at 7172.49,2586.86 h60
  text "9" at 5630.9,2487.65 h60
  text "62.99mil (1.600mm)" at 5947.64,2487.65 h60
  text "PTH" at 6568.66,2487.65 h60
  text "Round" at 6812.59,2487.65 h60
  text "Top Layer - Bottom Layer" at 7172.49,2487.65 h60
  text "5" at 5630.9,2388.44 h60
  text "63.00mil (1.600mm)" at 5947.64,2388.44 h60
  text "PTH" at 6568.66,2388.44 h60
  text "Round" at 6812.59,2388.44 h60
  text "Top Layer - Bottom Layer" at 7172.49,2388.44 h60
  text "4" at 5630.9,2289.23 h60
  text "150.00mil (3.810mm)" at 5947.64,2289.23 h60
  text "PTH" at 6568.66,2289.23 h60
  text "Round" at 6812.59,2289.23 h60
  text "Top Layer - Bottom Layer" at 7172.49,2289.23 h60
  text "296 Total" at 5630.9,2190.02 h60
  text ".Layer_Name" at 577,-858.49 h60
M17 Embedded Cavity:
  text ".Layer_Name" at 577,-858.49 h60
M18 Embedded Assembly:
  text ".Layer_Name" at 577,-858.49 h60
M19 Embedded Keepout:
  text ".Layer_Name" at 577,-858.49 h60

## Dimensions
0,-400 to 1000,-400 on M2 Board Dimensions
0,0 to 3700,0 on M2 Board Dimensions
0,0 to 0,4450 on M2 Board Dimensions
